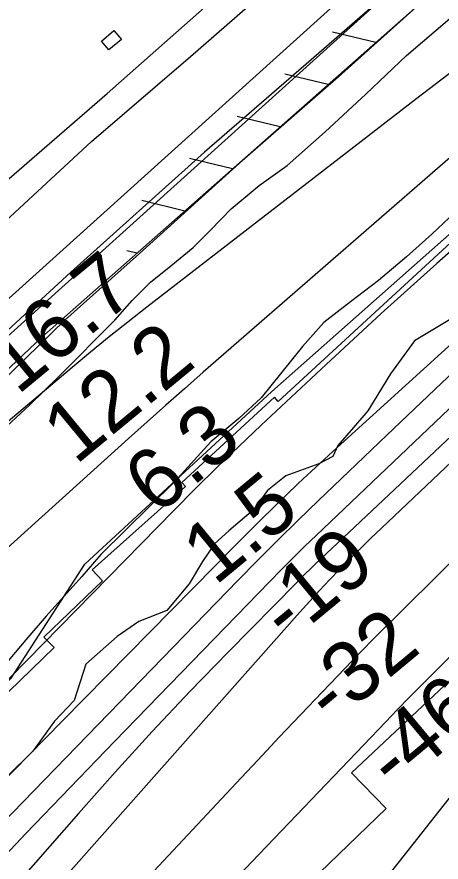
# Model space of a CAD drawing. Extents: x 3598634 to 3636690, y 517270 to 542944.
# Drawn here: x 3608151 to 3608618, y 532774 to 533703 of the extents above; entities that cross this region are included whole.
import ezdxf

# ---------------------------------------------------------------- set-up
doc = ezdxf.new("R2010")
doc.units = 0
for name, color, linetype in [('V-BLDG-OTLN', 7, 'Continuous'), ('V-FLOD-BASE', 7, 'Continuous'), ('V-LEVE-TOET', 7, 'Continuous'), ('V-RIVR-EDGE', 7, 'Continuous'), ('V-RIVR-RANG', 7, 'Continuous'), ('V-ROAD-CNTR', 7, 'Continuous'), ('V-RRAP-FSHR', 7, 'Continuous'), ('V-RRAP-RVMT', 7, 'Continuous'), ('V-SITE-VEGE', 7, 'Continuous'), ('V-SURV-LINE', 7, 'Continuous'), ('V-TOPO-DPTH', 7, 'Continuous'), ('V-TOPO-MAJR', 7, 'Continuous'), ('V-TOPO-MINR', 7, 'Continuous'), ('V-TOPO-WATR', 7, 'Continuous')]:
    doc.layers.add(name, color=color, linetype=linetype)

msp = doc.modelspace()

# ---------------------------------------------------------------- linework, layer by layer
at = {"layer": 'V-BLDG-OTLN'}
msp.add_lwpolyline([(3608266.215, 533678.681), (3608252.571, 533667.151), (3608244.416, 533676.797), (3608258.066, 533688.329)], close=True, dxfattribs=at)
at = {"layer": 'V-FLOD-BASE'}
msp.add_lwpolyline([(3608576.29, 533744.8640000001), (3608474.832, 533656.174), (3608357.713, 533554.6190000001), (3608210.6240000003, 533422.587), (3608085.315, 533307.471), (3607935.491, 533170.011), (3607759.122, 533012.93), (3607633.821, 532900.531), (3607492.19, 532777.311)], dxfattribs=at)
at = {"layer": 'V-LEVE-TOET'}
for points in [[(3608679.214, 533794.5650000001), (3608504.883, 533637.477), (3608395.933, 533542.694), (3608286.293, 533443.157), (3608203.896, 533370.033), (3608147.363, 533314.495), (3608091.512, 533260.9940000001), (3608000.247, 533174.312), (3607947.13, 533126.235), (3607881.076, 533067.331), (3607798.687, 532996.922), (3607679.522, 532891.981), (3607580.79, 532806.675), (3607479.336, 532720.023)], [(3607538.818, 532932.046), (3607675.703, 533057.996), (3607752.668, 533132.4940000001), (3607814.645, 533190.733), (3607880.699, 533249.637), (3607929.046, 533292.2930000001), (3607980.128, 533341.054), (3608099.284, 533442.6), (3608233.447, 533566.52), (3608342.39, 533659.946), (3608462.237, 533764.888)]]:
    msp.add_lwpolyline(points, dxfattribs=at)
at = {"layer": 'V-RIVR-EDGE'}
msp.add_lwpolyline([(3608627.0544421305, 533370.3535686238), (3608588.395299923, 533347.1655332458), (3608561.95880715, 533311.0800064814), (3608537.348363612, 533270.0881479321), (3608521.372104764, 533251.7458407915), (3608504.167369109, 533232.1811171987), (3608498.622557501, 533219.9402866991), (3608483.2847784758, 533212.012760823), (3608447.1007709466, 533198.6222381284), (3608426.84150925, 533182.7414298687), (3608411.4703982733, 533161.3339910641), (3608384.4529990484, 533138.1171690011), (3608368.487345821, 533124.0639250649), (3608355.5716733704, 533104.488595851), (3608340.805710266, 533080.0160253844), (3608316.224053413, 533050.6659098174), (3608285.5575858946, 533038.4871979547), (3608261.62046922, 533022.002756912), (3608227.232209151, 532991.4514361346), (3608214.2665387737, 532951.6562375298), (3608192.7651644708, 532929.0385029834), (3608168.787140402, 532896.0105324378), (3608141.1464122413, 532868.5061622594)], dxfattribs=at)
at = {"layer": 'V-ROAD-CNTR'}
msp.add_lwpolyline([(3607853.1350000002, 533268.979), (3608001.969, 533403.121), (3608036.108, 533432.786), (3608142.929, 533525.609), (3608250.507, 533619.09), (3608458.348, 533803.322)], dxfattribs=at)
at = {"layer": 'V-RRAP-FSHR'}
for p, q in [((3608545.913869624, 533675.3166231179), (3608498.4429645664, 533686.7566002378)), ((3608493.447974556, 533628.977715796), (3608445.9760695, 533640.4176929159)), ((3608440.9820794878, 533582.6388084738), (3608393.510174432, 533594.078785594)), ((3608388.5161844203, 533536.2999011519), (3608341.0442793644, 533547.7398782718)), ((3608336.0502893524, 533489.96099383), (3608288.5783842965, 533501.4009709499)), ((3608283.5843942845, 533443.6220865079), (3608272.3774166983, 533446.323081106))]:
    msp.add_line(p, q, dxfattribs=at)
for points in [[(3608321.7723179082, 533477.3510190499), (3608613.938733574, 533735.397502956), (3608800.291360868, 533902.4591688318), (3608883.358194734, 533990.8069921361), (3609015.288930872, 534095.0117837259), (3609025.33491078, 534104.238765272)], [(3605820.86382512, 530227.3894172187), (3606036.061521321, 530488.3844894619), (3606189.2990254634, 530713.2835616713), (3606419.5761456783, 531040.6747939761), (3606531.1368497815, 531185.7858341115), (3606653.304145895, 531360.7157542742), (3606830.6076980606, 531571.9730984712), (3606913.7257781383, 531664.9400105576), (3606995.6908342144, 531767.9892266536), (3607074.1906742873, 531873.2789547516), (3607165.5724343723, 531981.5730988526), (3607230.9753144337, 532060.8941869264), (3607289.867602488, 532131.0136109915), (3607473.880402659, 532321.0700591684), (3607836.054866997, 532677.0083635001), (3607900.3948350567, 532747.1503155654), (3608145.0202432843, 532976.3297077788), (3608226.1701953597, 533101.7266998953), (3608431.6276035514, 533291.5517240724), (3608655.69928376, 533489.6629562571), (3608731.274579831, 533575.8530363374), (3608845.2990279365, 533667.1917884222), (3608960.3638600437, 533749.2674364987)], [(3607274.64841216, 532541.5228907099), (3607598.048765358, 532823.70732634), (3607921.78711788, 533108.1767573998), (3608178.908603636, 533351.1702714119), (3608613.938733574, 533735.397502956)]]:
    msp.add_lwpolyline(points, dxfattribs=at)
at = {"layer": 'V-RRAP-RVMT'}
for p, q in [((3608637.6070000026, 533463.5920000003), (3608438.6320000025, 533280.5460000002)), ((3608434.3960000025, 533285.2870000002), (3608332.6830000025, 533191.285)), ((3608438.6320000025, 533280.5460000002), (3608434.3960000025, 533285.2870000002)), ((3608332.6830000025, 533191.285), (3608336.5710000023, 533186.8280000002)), ((3608336.5710000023, 533186.8280000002), (3608234.1230000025, 533095.4430000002)), ((3608234.1230000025, 533095.4430000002), (3608245.317564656, 533083.2584928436)), ((3608245.317564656, 533083.2584928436), (3608181.0730000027, 533021.2390000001)), ((3608181.0730000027, 533021.2390000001), (3608192.2460000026, 533009.924)), ((3608519.3750000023, 532872.2130000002), (3608669.5970000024, 533013.7700000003)), ((3608192.2460000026, 533009.924), (3608103.1310000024, 532923.719)), ((3608557.1770000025, 532833.0250000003), (3608519.3750000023, 532872.2130000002)), ((3608456.6170000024, 532735.9100000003), (3608557.1770000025, 532833.0250000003))]:
    msp.add_line(p, q, dxfattribs=at)
at = {"layer": 'V-SITE-VEGE'}
for p, q in [((3608579.651, 533660.884), (3608629.919, 533703.9230000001)), ((3608534.957, 533618.527), (3608579.651, 533660.884)), ((3608490.2660000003, 533576.8670000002), (3608534.957, 533618.527)), ((3608448.372, 533540.0720000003), (3608490.2660000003, 533576.8670000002)), ((3608417.664, 533517.872), (3608448.372, 533540.0720000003)), ((3608386.946, 533492.192), (3608417.664, 533517.872)), ((3608639.772, 533494.955), (3608607.647, 533464.403)), ((3608364.597, 533469.2710000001), (3608386.946, 533492.192)), ((3608345.038, 533449.825), (3608364.597, 533469.2710000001)), ((3608607.647, 533464.403), (3608579.718, 533439.409)), ((3608320.606, 533429.698), (3608345.038, 533449.825)), ((3608579.718, 533439.4090000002), (3608549.001, 533413.725)), ((3608298.268, 533411.655), (3608320.606, 533429.698)), ((3608278.0130000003, 533391.515), (3608298.268, 533411.655)), ((3608549.001, 533413.725), (3608518.289, 533390.134)), ((3608259.147, 533369.978), (3608278.0130000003, 533391.515)), ((3608518.289, 533390.1340000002), (3608488.972, 533367.234)), ((3608196.984, 533307.473), (3608259.147, 533369.978)), ((3608488.972, 533367.234), (3608465.217, 533340.8370000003)), ((3608465.217, 533340.8370000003), (3608419.786, 533284.552)), ((3608165.556, 533276.9170000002), (3608196.984, 533307.473)), ((3608419.786, 533284.552), (3608395.345, 533261.639)), ((3608111.091, 533226.231), (3608165.556, 533276.9170000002)), ((3608395.345, 533261.639), (3608364.627, 533235.957)), ((3608364.627, 533235.957), (3608324.806, 533192.193)), ((3608324.806, 533192.193), (3608243.789, 533112.3290000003)), ((3608243.789, 533112.3290000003), (3608222.826, 533088.013)), ((3608222.826, 533088.013), (3608183.699, 533044.2479999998)), ((3608183.699, 533044.2480000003), (3608161.339, 533018.541)), ((3608161.339, 533018.541), (3608127.7970000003, 532978.939))]:
    msp.add_line(p, q, dxfattribs=at)
at = {"layer": 'V-SURV-LINE'}
for points in [[(3607982.5078242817, 533249.5480409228), (3609039.452505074, 534202.9836780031)], [(3609059.5583790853, 534180.7181425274), (3608002.614103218, 533227.2828707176)]]:
    msp.add_lwpolyline(points, dxfattribs=at)
at = {"layer": 'V-TOPO-DPTH'}
for points in [[(3609278.5001712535, 533933.5956766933), (3608503.449095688, 533229.7901084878), (3608489.255443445, 533216.7930610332), (3608475.13462605, 533203.7180066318), (3608461.123060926, 533190.5259418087), (3608447.1843306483, 533177.2558700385), (3608433.357443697, 533163.8693486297), (3608419.6068220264, 533150.4055932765), (3608405.9705982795, 533136.8259870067), (3608392.4106398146, 533123.1691467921), (3608273.992108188, 533002.8911629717), (3608201.2971241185, 532929.0206530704), (3608128.6248490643, 532855.1278195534), (3608055.986637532, 532781.2015006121), (3607983.3711350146, 532707.2528580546), (3607541.4783495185, 532257.0399294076)], [(3607541.4783495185, 532257.0399294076), (3607983.3711350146, 532707.2528580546), (3608055.986637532, 532781.2015006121), (3608128.6248490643, 532855.1278195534), (3608201.2971241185, 532929.0206530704), (3608273.992108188, 533002.8911629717), (3608392.4106398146, 533123.1691467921), (3608405.9705982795, 533136.8259870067), (3608419.6068220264, 533150.4055932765), (3608433.357443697, 533163.8693486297), (3608447.1843306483, 533177.2558700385), (3608461.123060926, 533190.5259418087), (3608475.13462605, 533203.7180066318), (3608489.255443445, 533216.7930610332), (3608503.449095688, 533229.7901084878), (3609278.5001712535, 533933.5956766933)], [(3609282.584963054, 533874.5401358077), (3609091.247997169, 533702.7828415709), (3608983.6299711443, 533605.3252450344), (3608876.5858531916, 533507.24674469), (3608770.4025973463, 533408.2368886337), (3608664.7932495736, 533308.6061287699), (3608480.8088173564, 533133.5119626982), (3608467.6981051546, 533120.8858505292), (3608454.6885765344, 533108.1575379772), (3608441.830823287, 533095.2759248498), (3608429.07425362, 533082.2921113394), (3608258.604894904, 532906.7165803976), (3608161.2610271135, 532805.3337141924), (3608064.678899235, 532703.2382364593), (3607969.2393812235, 532600.073841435), (3607874.5616031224, 532496.1968348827), (3607613.8797606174, 532206.9684789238), (3607604.307241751, 532196.3432368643), (3607594.737684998, 532185.7153287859), (3607585.1725714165, 532175.0834216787), (3607575.610419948, 532164.4488485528), (3607441.354665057, 532015.0731620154)], [(3607441.354665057, 532015.0731620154), (3607575.610419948, 532164.4488485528), (3607585.1725714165, 532175.0834216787), (3607594.737684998, 532185.7153287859), (3607604.307241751, 532196.3432368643), (3607613.8797606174, 532206.9684789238), (3607874.5616031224, 532496.1968348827), (3607969.2393812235, 532600.073841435), (3608064.678899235, 532703.2382364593), (3608161.2610271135, 532805.3337141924), (3608258.604894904, 532906.7165803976), (3608429.07425362, 533082.2921113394), (3608441.830823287, 533095.2759248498), (3608454.6885765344, 533108.1575379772), (3608467.6981051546, 533120.8858505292), (3608480.8088173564, 533133.5119626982), (3608664.7932495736, 533308.6061287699), (3608770.4025973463, 533408.2368886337), (3608876.5858531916, 533507.24674469), (3608983.6299711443, 533605.3252450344), (3609091.247997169, 533702.7828415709), (3609282.584963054, 533874.5401358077)], [(3607761.756536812, 532061.8420105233), (3608070.940006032, 532407.7299699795), (3608154.5565031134, 532500.3363408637), (3608238.7840992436, 532592.3778493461), (3608323.9283439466, 532683.5720642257), (3608409.683687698, 532774.2014167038), (3608556.8758265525, 532928.2087829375), (3608569.5447898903, 532941.360415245), (3608582.2820881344, 532954.4450010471), (3608595.1218887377, 532967.4290170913), (3608608.030024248, 532980.3459866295), (3608754.478214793, 533125.7464296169), (3608840.7671019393, 533211.2062921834), (3608927.1965175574, 533296.5234415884), (3609013.836725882, 533381.6265212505), (3609100.617462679, 533466.5868877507), (3609393.7700248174, 533752.880796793)], [(3609393.7700248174, 533752.880796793), (3609100.617462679, 533466.5868877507), (3609013.836725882, 533381.6265212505), (3608927.1965175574, 533296.5234415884), (3608840.7671019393, 533211.2062921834), (3608754.478214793, 533125.7464296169), (3608608.030024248, 532980.3459866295), (3608595.1218887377, 532967.4290170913), (3608582.2820881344, 532954.4450010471), (3608569.5447898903, 532941.360415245), (3608556.8758265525, 532928.2087829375), (3608409.683687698, 532774.2014167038), (3608323.9283439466, 532683.5720642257), (3608238.7840992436, 532592.3778493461), (3608154.5565031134, 532500.3363408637), (3608070.940006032, 532407.7299699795), (3607761.756536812, 532061.8420105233)], [(3608839.0191137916, 533729.2974036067), (3608745.7274825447, 533650.5465240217), (3608653.111874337, 533570.9841752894), (3608356.299991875, 533312.6389762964), (3608335.6224398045, 533294.5466827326), (3608315.0079304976, 533276.3832125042), (3608294.487985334, 533258.112977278), (3608274.031082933, 533239.7715653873), (3608105.7390647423, 533088.0931887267), (3608001.1778853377, 532993.8653662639), (3607896.609302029, 532899.6457619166), (3607792.029612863, 532805.4384847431), (3607687.4425197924, 532711.2394256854), (3607394.9798662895, 532447.8566238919)], [(3607647.456580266, 532062.7259102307), (3607679.1488233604, 532098.3119338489), (3607681.625337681, 532101.072114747), (3607684.1153446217, 532103.8199780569), (3607686.6255904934, 532106.549364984), (3607689.1493289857, 532109.266434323), (3608392.4391153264, 532860.8429781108), (3608416.085211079, 532886.0312727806), (3608439.7851179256, 532911.1686698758), (3608463.565741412, 532936.2297206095), (3608487.4001759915, 532961.2398737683), (3608528.203715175, 533003.9185721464), (3608531.6913557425, 533007.5368427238), (3608535.198481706, 533011.1359705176), (3608538.7348357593, 533014.7063841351), (3608542.2906752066, 533018.2576549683), (3608858.5155658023, 533331.5116326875), (3608943.9548586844, 533415.5280905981), (3609029.8023927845, 533499.1222068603), (3609116.262288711, 533582.0828106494), (3609203.1304258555, 533664.6210727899)], [(3609203.1304258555, 533664.6210727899), (3609116.262288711, 533582.0828106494), (3609029.8023927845, 533499.1222068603), (3608943.9548586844, 533415.5280905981), (3608858.5155658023, 533331.5116326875), (3608542.2906752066, 533018.2576549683), (3608538.7348357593, 533014.7063841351), (3608535.198481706, 533011.1359705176), (3608531.6913557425, 533007.5368427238), (3608528.203715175, 533003.9185721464), (3608487.4001759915, 532961.2398737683), (3608463.565741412, 532936.2297206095), (3608439.7851179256, 532911.1686698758), (3608416.085211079, 532886.0312727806), (3608392.4391153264, 532860.8429781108), (3607689.1493289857, 532109.266434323), (3607686.6255904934, 532106.549364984), (3607684.1153446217, 532103.8199780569), (3607681.625337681, 532101.072114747), (3607679.1488233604, 532098.3119338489), (3607647.456580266, 532062.7259102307)], [(3607295.3812890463, 531733.6500398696), (3607612.8538788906, 532094.702802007), (3607631.004029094, 532115.2799605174), (3607649.196633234, 532135.8193981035), (3607667.4529182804, 532156.3022543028), (3607685.7516572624, 532176.7473895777), (3607793.558679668, 532296.824284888), (3607865.7218247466, 532377.3428985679), (3607937.7903754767, 532457.9459410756), (3608009.7170346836, 532538.6756268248), (3608081.549099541, 532619.489741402), (3608462.5011577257, 533048.8368106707), (3608473.26961942, 533060.8162101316), (3608484.1400110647, 533072.7011623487), (3608495.1632976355, 533084.4444437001), (3608506.2885141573, 533096.0932778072), (3608517.5682551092, 533107.5921858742), (3608528.952013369, 533118.9857228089), (3608540.491797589, 533130.2212030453), (3608552.1355991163, 533141.3513121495), (3608629.667054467, 533214.445897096)], [(3608629.667054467, 533214.445897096), (3608552.1355991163, 533141.3513121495), (3608540.491797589, 533130.2212030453), (3608528.952013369, 533118.9857228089), (3608517.5682551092, 533107.5921858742), (3608506.2885141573, 533096.0932778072), (3608495.1632976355, 533084.4444437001), (3608484.1400110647, 533072.7011623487), (3608473.26961942, 533060.8162101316), (3608462.5011577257, 533048.8368106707), (3608081.549099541, 532619.489741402), (3608009.7170346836, 532538.6756268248), (3607937.7903754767, 532457.9459410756), (3607865.7218247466, 532377.3428985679), (3607793.558679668, 532296.824284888), (3607685.7516572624, 532176.7473895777), (3607667.4529182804, 532156.3022543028), (3607649.196633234, 532135.8193981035), (3607631.004029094, 532115.2799605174), (3607612.8538788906, 532094.702802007), (3607295.3812890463, 531733.6500398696)]]:
    msp.add_lwpolyline(points, dxfattribs=at)
at = {"layer": 'V-TOPO-MAJR'}
msp.add_lwpolyline([(3609300.3634407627, 533552.8491525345), (3609016.7187628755, 533269.8300182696), (3608953.5202149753, 533205.6550992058), (3608891.086745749, 533140.7569662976), (3608829.8008945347, 533074.774012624), (3608769.280121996, 533008.0678451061), (3608670.142443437, 532896.8536778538), (3608659.874806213, 532885.1195735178), (3608649.7538251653, 532873.2626004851), (3608639.852828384, 532861.2213244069), (3608630.0984877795, 532849.0571796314), (3608571.473402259, 532774.5537446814), (3608553.4615599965, 532751.3866396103), (3608535.631783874, 532728.081917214), (3608518.0751069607, 532704.57076883), (3608500.7004961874, 532680.9220031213), (3608483.6076753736, 532657.06900385), (3608466.708385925, 532633.0813991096), (3608450.0993935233, 532608.8918861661), (3608433.683932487, 532584.5677677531), (3608012.1101972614, 531821.0103381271)], dxfattribs=at)
at = {"layer": 'V-TOPO-MINR'}
for points in [[(3609223.915346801, 533954.599584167), (3608737.174201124, 533540.4757134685), (3608674.837619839, 533486.6816043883), (3608613.0130186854, 533432.313459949), (3608551.956387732, 533377.084262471), (3608491.411736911, 533321.2810296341), (3608419.962379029, 533254.4950059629), (3608395.679328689, 533231.4976100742), (3608371.599880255, 533208.2916932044), (3608347.8258346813, 533184.7729948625), (3608324.2553910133, 533161.0457755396), (3607639.99524579, 532463.1694893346), (3607612.6995803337, 532435.0413486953), (3607585.599964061, 532406.727498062), (3607558.7944215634, 532378.1350824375), (3607532.184928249, 532349.3569568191)], [(3609251.8750106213, 533877.2427907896), (3608801.855911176, 533470.5025605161), (3608740.332455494, 533414.403539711), (3608679.1407860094, 533357.9480489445), (3608618.44679582, 533300.9578532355), (3608558.0845918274, 533243.6111875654), (3608482.8802259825, 533171.5334969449), (3608460.4882515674, 533149.8383593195), (3608438.255117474, 533127.9833756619), (3608416.2602438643, 533105.8886229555), (3608394.424210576, 533083.6340242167), (3607874.7256928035, 532548.1976372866), (3607821.8964364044, 532493.4515041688), (3607769.28043001, 532438.5023588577), (3607716.9842986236, 532383.2486952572), (3607664.901417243, 532327.7920194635), (3607611.74496276, 532270.861981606), (3607586.4297840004, 532243.6906844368), (3607561.1539720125, 532216.482895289), (3607535.9372101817, 532189.2203681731)], [(3609282.584963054, 533874.5401358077), (3609091.247997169, 533702.7828415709), (3608983.6299711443, 533605.3252450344), (3608876.5858531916, 533507.24674469), (3608770.4025973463, 533408.2368886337), (3608664.7932495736, 533308.6061287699), (3608480.8088173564, 533133.5119626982), (3608467.6981051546, 533120.8858505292), (3608454.6885765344, 533108.1575379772), (3608441.830823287, 533095.2759248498), (3608429.07425362, 533082.2921113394), (3608258.604894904, 532906.7165803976), (3608161.2610271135, 532805.3337141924), (3608064.678899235, 532703.2382364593), (3607969.2393812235, 532600.073841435), (3607874.5616031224, 532496.1968348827), (3607613.8797606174, 532206.9684789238), (3607604.307241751, 532196.3432368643), (3607594.737684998, 532185.7153287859), (3607585.1725714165, 532175.0834216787), (3607575.610419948, 532164.4488485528), (3607441.354665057, 532015.0731620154)], [(3608790.558722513, 533765.498688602), (3608689.947779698, 533689.3136096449), (3608589.7578000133, 533612.5677614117), (3608294.128591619, 533384.153739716), (3608273.339258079, 533367.8779649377), (3608252.691174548, 533351.4272065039), (3608232.254966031, 533334.7139725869), (3608211.960007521, 533317.8257550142), (3608092.2310816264, 533216.8931201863), (3608012.8650134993, 533148.6439975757), (3607934.4146307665, 533079.3780470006), (3607857.3377761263, 533008.5868544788), (3607781.17660688, 532936.7788339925), (3607320.225775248, 532493.5546481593)], [(3609393.7700248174, 533752.880796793), (3609100.617462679, 533466.5868877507), (3609013.836725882, 533381.6265212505), (3608927.1965175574, 533296.5234415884), (3608840.7671019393, 533211.2062921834), (3608754.478214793, 533125.7464296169), (3608608.030024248, 532980.3459866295), (3608595.1218887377, 532967.4290170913), (3608582.2820881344, 532954.4450010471), (3608569.5447898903, 532941.360415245), (3608556.8758265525, 532928.2087829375), (3608409.683687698, 532774.2014167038), (3608323.9283439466, 532683.5720642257), (3608238.7840992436, 532592.3778493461), (3608154.5565031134, 532500.3363408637), (3608070.940006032, 532407.7299699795), (3607761.756536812, 532061.8420105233)], [(3608839.0191137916, 533729.2974036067), (3608745.7274825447, 533650.5465240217), (3608653.111874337, 533570.9841752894), (3608356.299991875, 533312.6389762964), (3608335.6224398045, 533294.5466827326), (3608315.0079304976, 533276.3832125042), (3608294.487985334, 533258.112977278), (3608274.031082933, 533239.7715653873), (3608105.7390647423, 533088.0931887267), (3608001.1778853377, 532993.8653662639), (3607896.609302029, 532899.6457619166), (3607792.029612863, 532805.4384847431), (3607687.4425197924, 532711.2394256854), (3607394.9798662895, 532447.8566238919)], [(3609203.1304258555, 533664.6210727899), (3609116.262288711, 533582.0828106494), (3609029.8023927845, 533499.1222068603), (3608943.9548586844, 533415.5280905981), (3608858.5155658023, 533331.5116326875), (3608542.2906752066, 533018.2576549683), (3608538.7348357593, 533014.7063841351), (3608535.198481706, 533011.1359705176), (3608531.6913557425, 533007.5368427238), (3608528.203715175, 533003.9185721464), (3608487.4001759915, 532961.2398737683), (3608463.565741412, 532936.2297206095), (3608439.7851179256, 532911.1686698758), (3608416.085211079, 532886.0312727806), (3608392.4391153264, 532860.8429781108), (3607689.1493289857, 532109.266434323), (3607686.6255904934, 532106.549364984), (3607684.1153446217, 532103.8199780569), (3607681.625337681, 532101.072114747), (3607679.1488233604, 532098.3119338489), (3607647.456580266, 532062.7259102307)], [(3608936.9898316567, 533532.6367101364), (3608478.9556662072, 533101.0718652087), (3608473.81471606, 533096.171811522), (3608468.7119123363, 533091.2327978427), (3608463.6663282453, 533086.2353441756), (3608458.658890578, 533081.198930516), (3608383.723635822, 533004.956910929), (3608341.6531988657, 532961.4210112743), (3608300.083774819, 532917.4197580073), (3608259.2658701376, 532872.7204743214), (3608218.9489783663, 532827.5558370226), (3608055.9154751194, 532641.77406112)], [(3608629.667054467, 533214.445897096), (3608552.1355991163, 533141.3513121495), (3608540.491797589, 533130.2212030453), (3608528.952013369, 533118.9857228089), (3608517.5682551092, 533107.5921858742), (3608506.2885141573, 533096.0932778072), (3608495.1632976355, 533084.4444437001), (3608484.1400110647, 533072.7011623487), (3608473.26961942, 533060.8162101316), (3608462.5011577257, 533048.8368106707), (3608081.549099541, 532619.489741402), (3608009.7170346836, 532538.6756268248), (3607937.7903754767, 532457.9459410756), (3607865.7218247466, 532377.3428985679), (3607793.558679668, 532296.824284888), (3607685.7516572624, 532176.7473895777), (3607667.4529182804, 532156.3022543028), (3607649.196633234, 532135.8193981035), (3607631.004029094, 532115.2799605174), (3607612.8538788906, 532094.702802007), (3607295.3812890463, 531733.6500398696)]]:
    msp.add_lwpolyline(points, dxfattribs=at)
at = {"layer": 'V-TOPO-WATR'}
msp.add_lwpolyline([(3609278.5001712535, 533933.5956766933), (3608503.449095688, 533229.7901084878), (3608489.255443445, 533216.7930610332), (3608475.13462605, 533203.7180066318), (3608461.123060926, 533190.5259418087), (3608447.1843306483, 533177.2558700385), (3608433.357443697, 533163.8693486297), (3608419.6068220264, 533150.4055932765), (3608405.9705982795, 533136.8259870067), (3608392.4106398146, 533123.1691467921), (3608273.992108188, 533002.8911629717), (3608201.2971241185, 532929.0206530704), (3608128.6248490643, 532855.1278195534), (3608055.986637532, 532781.2015006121), (3607983.3711350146, 532707.2528580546), (3607541.4783495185, 532257.0399294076)], dxfattribs=at)

# ---------------------------------------------------------------- texts
at = {"layer": 'V-RIVR-RANG'}
for s, height, rotation, p in [('16.7', 67, 39.55832571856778, (3608152.0193854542, 533286.7460961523)), ('12.2', 67, 39.55832571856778, (3608215.8923854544, 533209.8030961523)), ('6.3', 67, 39.55832571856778, (3608305.389736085, 533154.0270280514)), ('1.5', 67, 39.55832571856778, (3608369.262736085, 533077.0840280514)), ('-19', 67, 39.55832571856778, (3608449.4061650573, 533013.5803498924)), ('-32', 67.00000000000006, 39.83894444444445, (3608498.0109730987, 532923.4877240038)), ('-46', 67.00000000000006, 39.83894444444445, (3608566.7449967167, 532850.6003770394))]:
    msp.add_text(s, height=height, rotation=rotation, dxfattribs=at).set_placement(p)

doc.saveas('drawing.dxf')
